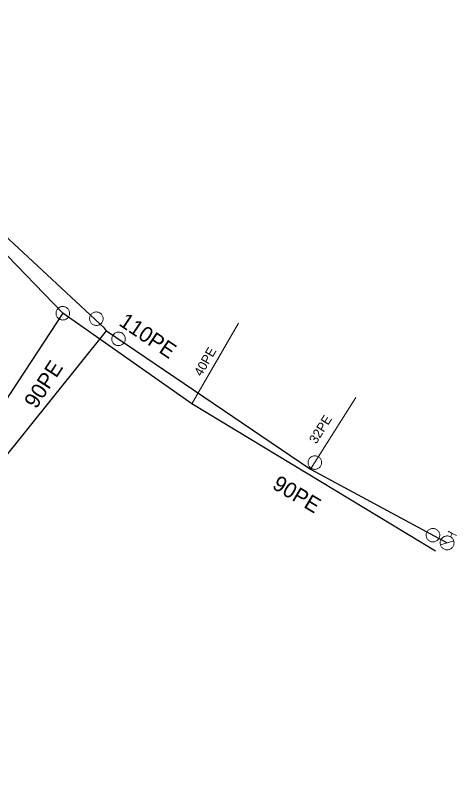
# Model space of a CAD drawing. Extents: x -741806 to -738704, y -1059275 to -1055387.
# Drawn here: x -740289 to -740260.5, y -1057228.9 to -1057178.6 of the extents above; entities that cross this region are included whole.
import ezdxf

# ---------------------------------------------------------------- set-up
doc = ezdxf.new("R2010")
doc.units = 0
doc.header["$LTSCALE"] = 0.4
for name, color, linetype, lineweight in [('2', 7, 'Continuous', 25), ('21', 7, 'Continuous', 13), ('3', 7, 'Continuous', 13), ('50', 7, 'Continuous', 13), ('51', 7, 'Continuous', 13), ('52', 7, 'Continuous', 25), ('56', 7, 'Continuous', 13)]:
    doc.layers.add(name, color=color, linetype=linetype, lineweight=lineweight)
for name, color, linetype in [('5', 7, 'Continuous'), ('53', 7, 'Continuous'), ('54', 7, 'Continuous'), ('55', 7, 'Continuous')]:
    doc.layers.add(name, color=color, linetype=linetype)

msp = doc.modelspace()

# ---------------------------------------------------------------- linework, layer by layer
at = {"layer": '2'}
for points in [[(-740262.96, -1057069.909), (-740269.19, -1057072.669), (-740274.949, -1057077.7), (-740275.559, -1057078.32), (-740280.173, -1057082.526), (-740281.937, -1057084.151), (-740283.887, -1057086.098), (-740285.828, -1057088.145), (-740287.55, -1057089.96), (-740294.199, -1057098.5), (-740299.28, -1057106.06), (-740302.629, -1057112.73), (-740305.219, -1057120.72), (-740306.46, -1057125.389), (-740308.809, -1057139.85), (-740308.96, -1057146.77), (-740308.55, -1057154.01), (-740307.079, -1057159.62), (-740305.57, -1057163.75), (-740300.92, -1057174.76), (-740300.27, -1057176.629), (-740296.46, -1057184.19), (-740290.177, -1057193.486), (-740285.949, -1057197.84)], [(-740285.949, -1057197.84), (-740290.513, -1057204.772), (-740294.12, -1057210.94), (-740300.07, -1057216.52), (-740301.579, -1057218.07), (-740303.1, -1057220.48), (-740304.059, -1057223.3), (-740304.57, -1057225.659), (-740305.55, -1057231.639), (-740307.182, -1057240.935), (-740308.309, -1057246.08), (-740308.647, -1057246.469)], [(-740261.89, -1057213.2), (-740277.62, -1057203.7), (-740285.949, -1057197.84)]]:
    msp.add_lwpolyline(points, dxfattribs=at)
at = {"layer": '21'}
msp.add_line((-740269.949, -1057207.919), (-740267.02, -1057203.28), dxfattribs=at)
at = {"layer": '3'}
msp.add_lwpolyline([(-740285.633, -1057198.143), (-740285.604, -1057198.109), (-740285.578, -1057198.071), (-740285.555, -1057198.031), (-740285.538, -1057197.989), (-740285.524, -1057197.945), (-740285.515, -1057197.9), (-740285.512, -1057197.854), (-740285.512, -1057197.808), (-740285.519, -1057197.763), (-740285.529, -1057197.719), (-740285.544, -1057197.675), (-740285.563, -1057197.633), (-740285.587, -1057197.595), (-740285.614, -1057197.558), (-740285.646, -1057197.525), (-740285.681, -1057197.494), (-740285.719, -1057197.469), (-740285.758, -1057197.446), (-740285.801, -1057197.429), (-740285.845, -1057197.416), (-740285.89, -1057197.407), (-740285.934, -1057197.403), (-740285.981, -1057197.404), (-740286.026, -1057197.409), (-740286.071, -1057197.42), (-740286.114, -1057197.436), (-740286.155, -1057197.454), (-740286.195, -1057197.479), (-740286.231, -1057197.506), (-740286.265, -1057197.538), (-740286.295, -1057197.572), (-740286.321, -1057197.609), (-740286.343, -1057197.65), (-740286.361, -1057197.693), (-740286.374, -1057197.735), (-740286.383, -1057197.781), (-740286.386, -1057197.826), (-740286.385, -1057197.873), (-740286.379, -1057197.917), (-740286.369, -1057197.962), (-740286.354, -1057198.005), (-740286.335, -1057198.047), (-740286.312, -1057198.086), (-740286.284, -1057198.123), (-740286.252, -1057198.156), (-740286.218, -1057198.186), (-740286.18, -1057198.212), (-740286.14, -1057198.234), (-740286.097, -1057198.252), (-740286.053, -1057198.265), (-740286.009, -1057198.273), (-740285.963, -1057198.278), (-740285.917, -1057198.276), (-740285.872, -1057198.271), (-740285.827, -1057198.26), (-740285.784, -1057198.245), (-740285.743, -1057198.226), (-740285.703, -1057198.202), (-740285.667, -1057198.174), (-740285.634, -1057198.144)], dxfattribs=at)
at = {"layer": '50'}
for p, q in [((-740261.072, -1057211.911), (-740260.801, -1057212.057)), ((-740260.92, -1057212.278), (-740260.801, -1057212.057)), ((-740260.53, -1057212.203), (-740260.801, -1057212.057)), ((-740261.131, -1057212.672), (-740261.56, -1057212.801)), ((-740261.131, -1057212.672), (-740260.705, -1057212.547))]:
    msp.add_line(p, q, dxfattribs=at)
msp.add_lwpolyline([(-740260.742, -1057212.887), (-740260.721, -1057212.842), (-740260.704, -1057212.799), (-740260.693, -1057212.752), (-740260.688, -1057212.706), (-740260.686, -1057212.662), (-740260.69, -1057212.613), (-740260.699, -1057212.569), (-740260.711, -1057212.522), (-740260.728, -1057212.479), (-740260.752, -1057212.439), (-740260.777, -1057212.4), (-740260.806, -1057212.363), (-740260.842, -1057212.333), (-740260.879, -1057212.304), (-740260.918, -1057212.279), (-740260.96, -1057212.26), (-740261.002, -1057212.243), (-740261.048, -1057212.233), (-740261.095, -1057212.227), (-740261.143, -1057212.225), (-740261.188, -1057212.229), (-740261.235, -1057212.237), (-740261.279, -1057212.251), (-740261.321, -1057212.268), (-740261.364, -1057212.29), (-740261.403, -1057212.316), (-740261.437, -1057212.346), (-740261.472, -1057212.38), (-740261.498, -1057212.418), (-740261.525, -1057212.456), (-740261.545, -1057212.499), (-740261.56, -1057212.544), (-740261.571, -1057212.587), (-740261.578, -1057212.635), (-740261.578, -1057212.681), (-740261.576, -1057212.728), (-740261.566, -1057212.773), (-740261.555, -1057212.819), (-740261.536, -1057212.863), (-740261.513, -1057212.902), (-740261.486, -1057212.942), (-740261.456, -1057212.977), (-740261.425, -1057213.009), (-740261.385, -1057213.04), (-740261.346, -1057213.064), (-740261.304, -1057213.083), (-740261.26, -1057213.098), (-740261.214, -1057213.11), (-740261.169, -1057213.116), (-740261.12, -1057213.118), (-740261.076, -1057213.114), (-740261.028, -1057213.106), (-740260.985, -1057213.093), (-740260.942, -1057213.076), (-740260.901, -1057213.052), (-740260.861, -1057213.028), (-740260.825, -1057212.997), (-740260.795, -1057212.962), (-740260.766, -1057212.926)], close=True, dxfattribs=at)
at = {"layer": '51'}
for points in [[(-740284.068, -1057197.862), (-740284.101, -1057197.893), (-740284.131, -1057197.928), (-740284.157, -1057197.966), (-740284.179, -1057198.005), (-740284.196, -1057198.048), (-740284.21, -1057198.092), (-740284.217, -1057198.137), (-740284.222, -1057198.183), (-740284.219, -1057198.228), (-740284.214, -1057198.274), (-740284.203, -1057198.318), (-740284.188, -1057198.362), (-740284.168, -1057198.403), (-740284.145, -1057198.442), (-740284.116, -1057198.478), (-740284.085, -1057198.512), (-740284.05, -1057198.542), (-740284.012, -1057198.567), (-740283.972, -1057198.589), (-740283.929, -1057198.606), (-740283.885, -1057198.619), (-740283.841, -1057198.628), (-740283.795, -1057198.631), (-740283.749, -1057198.63), (-740283.703, -1057198.624), (-740283.659, -1057198.613), (-740283.616, -1057198.598), (-740283.574, -1057198.578), (-740283.535, -1057198.554), (-740283.499, -1057198.526), (-740283.466, -1057198.495), (-740283.437, -1057198.46), (-740283.41, -1057198.422), (-740283.389, -1057198.382), (-740283.371, -1057198.34), (-740283.358, -1057198.295), (-740283.35, -1057198.251), (-740283.346, -1057198.205), (-740283.348, -1057198.159), (-740283.354, -1057198.114), (-740283.364, -1057198.069), (-740283.38, -1057198.026), (-740283.4, -1057197.985), (-740283.423, -1057197.946), (-740283.451, -1057197.909), (-740283.483, -1057197.876), (-740283.518, -1057197.847), (-740283.555, -1057197.82), (-740283.596, -1057197.799), (-740283.639, -1057197.781), (-740283.682, -1057197.769), (-740283.727, -1057197.76), (-740283.773, -1057197.757), (-740283.818, -1057197.757), (-740283.864, -1057197.764), (-740283.909, -1057197.775), (-740283.951, -1057197.79), (-740283.993, -1057197.81), (-740284.032, -1057197.834), (-740284.067, -1057197.862)], [(-740281.991, -1057199.742), (-740281.968, -1057199.704), (-740281.948, -1057199.663), (-740281.933, -1057199.619), (-740281.922, -1057199.575), (-740281.917, -1057199.529), (-740281.916, -1057199.483), (-740281.92, -1057199.438), (-740281.928, -1057199.393), (-740281.942, -1057199.349), (-740281.959, -1057199.307), (-740281.981, -1057199.267), (-740282.007, -1057199.229), (-740282.037, -1057199.194), (-740282.07, -1057199.163), (-740282.107, -1057199.135), (-740282.146, -1057199.111), (-740282.188, -1057199.092), (-740282.231, -1057199.077), (-740282.276, -1057199.067), (-740282.322, -1057199.061), (-740282.367, -1057199.061), (-740282.413, -1057199.063), (-740282.458, -1057199.073), (-740282.501, -1057199.085), (-740282.544, -1057199.104), (-740282.584, -1057199.126), (-740282.621, -1057199.152), (-740282.656, -1057199.182), (-740282.687, -1057199.215), (-740282.716, -1057199.252), (-740282.738, -1057199.291), (-740282.758, -1057199.332), (-740282.773, -1057199.376), (-740282.784, -1057199.419), (-740282.789, -1057199.465), (-740282.791, -1057199.511), (-740282.786, -1057199.557), (-740282.778, -1057199.602), (-740282.764, -1057199.645), (-740282.747, -1057199.687), (-740282.725, -1057199.728), (-740282.699, -1057199.766), (-740282.669, -1057199.8), (-740282.636, -1057199.832), (-740282.599, -1057199.859), (-740282.56, -1057199.883), (-740282.518, -1057199.902), (-740282.475, -1057199.918), (-740282.43, -1057199.928), (-740282.385, -1057199.933), (-740282.339, -1057199.934), (-740282.294, -1057199.931), (-740282.249, -1057199.922), (-740282.205, -1057199.909), (-740282.162, -1057199.891), (-740282.122, -1057199.869), (-740282.085, -1057199.843), (-740282.05, -1057199.813), (-740282.019, -1057199.779), (-740281.992, -1057199.743)], [(-740269.443, -1057207.118), (-740269.482, -1057207.096), (-740269.524, -1057207.078), (-740269.568, -1057207.064), (-740269.612, -1057207.055), (-740269.658, -1057207.051), (-740269.704, -1057207.051), (-740269.749, -1057207.057), (-740269.794, -1057207.067), (-740269.837, -1057207.082), (-740269.879, -1057207.101), (-740269.918, -1057207.124), (-740269.956, -1057207.152), (-740269.989, -1057207.182), (-740270.019, -1057207.217), (-740270.046, -1057207.254), (-740270.068, -1057207.294), (-740270.087, -1057207.336), (-740270.1, -1057207.38), (-740270.108, -1057207.425), (-740270.113, -1057207.471), (-740270.112, -1057207.517), (-740270.107, -1057207.562), (-740270.096, -1057207.607), (-740270.082, -1057207.65), (-740270.063, -1057207.692), (-740270.039, -1057207.731), (-740270.012, -1057207.767), (-740269.981, -1057207.802), (-740269.946, -1057207.832), (-740269.909, -1057207.859), (-740269.869, -1057207.88), (-740269.828, -1057207.898), (-740269.783, -1057207.912), (-740269.739, -1057207.921), (-740269.693, -1057207.925), (-740269.647, -1057207.925), (-740269.602, -1057207.919), (-740269.557, -1057207.91), (-740269.514, -1057207.894), (-740269.473, -1057207.875), (-740269.433, -1057207.852), (-740269.396, -1057207.825), (-740269.363, -1057207.793), (-740269.332, -1057207.759), (-740269.306, -1057207.722), (-740269.283, -1057207.682), (-740269.266, -1057207.639), (-740269.251, -1057207.596), (-740269.243, -1057207.551), (-740269.239, -1057207.505), (-740269.24, -1057207.459), (-740269.244, -1057207.414), (-740269.255, -1057207.369), (-740269.269, -1057207.326), (-740269.289, -1057207.284), (-740269.312, -1057207.245), (-740269.339, -1057207.209), (-740269.371, -1057207.174), (-740269.405, -1057207.145), (-740269.442, -1057207.119)], [(-740261.662, -1057212.382), (-740261.642, -1057212.342), (-740261.627, -1057212.299), (-740261.616, -1057212.253), (-740261.611, -1057212.209), (-740261.61, -1057212.163), (-740261.613, -1057212.117), (-740261.622, -1057212.072), (-740261.635, -1057212.028), (-740261.653, -1057211.986), (-740261.675, -1057211.946), (-740261.701, -1057211.908), (-740261.731, -1057211.873), (-740261.764, -1057211.841), (-740261.8, -1057211.814), (-740261.84, -1057211.79), (-740261.881, -1057211.77), (-740261.924, -1057211.755), (-740261.968, -1057211.745), (-740262.014, -1057211.739), (-740262.06, -1057211.738), (-740262.106, -1057211.742), (-740262.151, -1057211.75), (-740262.194, -1057211.764), (-740262.237, -1057211.781), (-740262.277, -1057211.803), (-740262.315, -1057211.829), (-740262.349, -1057211.859), (-740262.381, -1057211.893), (-740262.408, -1057211.929), (-740262.433, -1057211.968), (-740262.452, -1057212.009), (-740262.467, -1057212.052), (-740262.477, -1057212.097), (-740262.483, -1057212.142), (-740262.484, -1057212.188), (-740262.481, -1057212.234), (-740262.472, -1057212.279), (-740262.459, -1057212.323), (-740262.441, -1057212.365), (-740262.419, -1057212.405), (-740262.393, -1057212.443), (-740262.363, -1057212.478), (-740262.33, -1057212.509), (-740262.294, -1057212.537), (-740262.254, -1057212.561), (-740262.213, -1057212.581), (-740262.17, -1057212.595), (-740262.126, -1057212.606), (-740262.08, -1057212.612), (-740262.034, -1057212.612), (-740261.988, -1057212.608), (-740261.943, -1057212.601), (-740261.9, -1057212.587), (-740261.857, -1057212.57), (-740261.817, -1057212.547), (-740261.779, -1057212.521), (-740261.745, -1057212.492), (-740261.713, -1057212.458), (-740261.686, -1057212.422), (-740261.662, -1057212.383)]]:
    msp.add_lwpolyline(points, dxfattribs=at)
at = {"layer": '52'}
for points in [[(-740283.129, -1057198.97), (-740283.26, -1057198.81), (-740289.74, -1057192.772), (-740295.66, -1057184.32), (-740299.64, -1057176.48), (-740305.079, -1057163.11), (-740306.469, -1057159.919), (-740308.03, -1057153.929), (-740308.37, -1057146.06), (-740307.77, -1057139.98), (-740305.71, -1057125.55), (-740304.82, -1057121.77), (-740302.16, -1057112.889), (-740299.12, -1057106.889), (-740298.43, -1057105.73), (-740293.78, -1057098.919), (-740287, -1057090.56), (-740282.309, -1057085.5), (-740278.449, -1057081.76), (-740275.899, -1057079.48), (-740275.289, -1057078.97), (-740268.949, -1057073.48), (-740263.329, -1057070.639), (-740262.78, -1057070.48)], [(-740317.443, -1057290.145), (-740317.35, -1057289.69), (-740316.219, -1057284.629), (-740312.52, -1057267.659), (-740311.399, -1057262.36), (-740306.51, -1057241.179), (-740304.539, -1057230.81), (-740303.309, -1057224.83), (-740302.359, -1057220.52), (-740301.14, -1057219.159), (-740299.39, -1057217.389), (-740295.62, -1057213.96), (-740293.44, -1057211.81), (-740283.129, -1057198.97)], [(-740283.129, -1057198.97), (-740269.949, -1057207.919), (-740261.129, -1057212.669)]]:
    msp.add_lwpolyline(points, dxfattribs=at)
at = {"layer": '56'}
msp.add_line((-740274.6, -1057198.48), (-740277.62, -1057203.7), dxfattribs=at)

# ---------------------------------------------------------------- texts
at = {"layer": '5'}
for rotation, p in [(57, (-740287.672, -1057204.067)), (329, (-740272.492, -1057209.115))]:
    msp.add_text('90PE', height=1, rotation=rotation, dxfattribs=at).set_placement(p)
at = {"layer": '53'}
msp.add_text('110PE ', height=1, rotation=326, dxfattribs=at).set_placement((-740282.397, -1057198.578))
at = {"layer": '54'}
msp.add_text('32PE', height=0.6, rotation=58, dxfattribs=at).set_placement((-740269.583, -1057206.324))
at = {"layer": '55'}
msp.add_text('40PE', height=0.6, rotation=60, dxfattribs=at).set_placement((-740276.996, -1057201.962))

doc.saveas('drawing.dxf')
